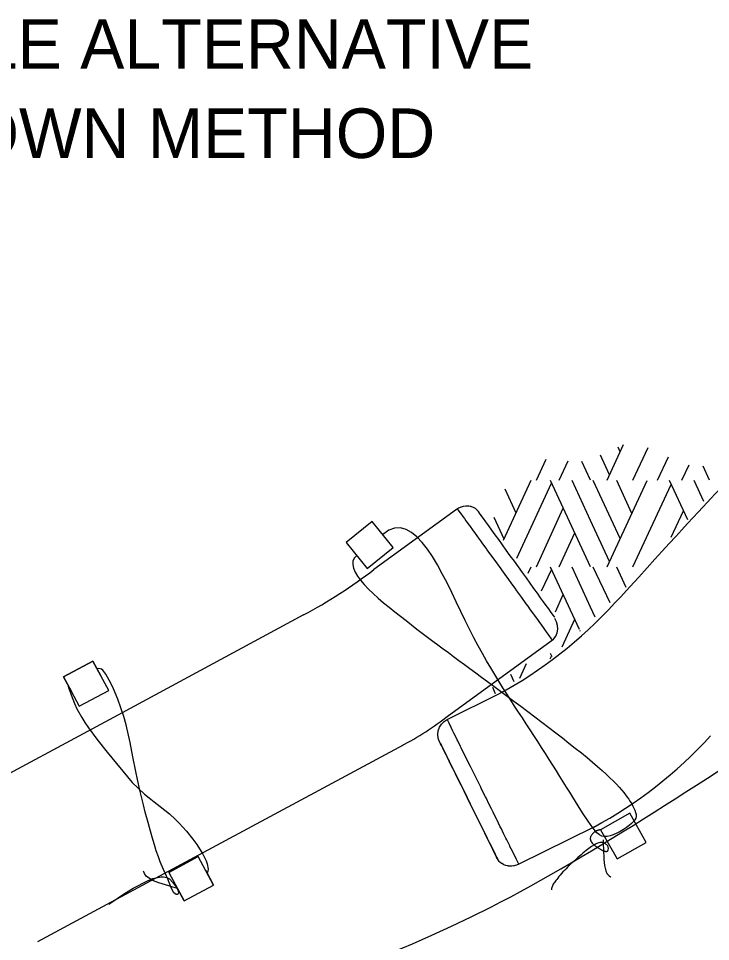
# Model space of a CAD drawing. Extents: x 99862 to 103680, y 99470 to 102076.
# Drawn here: x 100169.1 to 100392.4, y 101460 to 101757.9 of the extents above; entities that cross this region are included whole.
import ezdxf

# ---------------------------------------------------------------- set-up
doc = ezdxf.new("R2010")
doc.units = 0
for name, color, linetype in [('Level 10', 7, 'Continuous'), ('Level 11', 7, 'Continuous'), ('Level 17', 7, 'Continuous'), ('Level 20', 7, 'Continuous'), ('Level 4', 7, 'Continuous'), ('Level 6', 7, 'Continuous'), ('Level 8', 7, 'Continuous')]:
    doc.layers.add(name, color=color, linetype=linetype)

msp = doc.modelspace()

# ---------------------------------------------------------------- linework, layer by layer
at = {"layer": 'Level 10'}
msp.add_line((100327.99, 101542.55), (100327.99, 101542.55), dxfattribs=at)
at = {"layer": 'Level 11'}
for p, q in [((100359.08, 101608.87), (100364.39, 101620.37)), ((100363.32, 101618.05), (100362.61, 101619.55)), ((100367.38, 101608.87), (100372.3, 101619.43)), ((100359.85, 101610.6), (100356.9, 101616.92)), ((100375.34, 101608.87), (100378.85, 101616.43)), ((100336.24, 101608.87), (100339.34, 101615.67)), ((100343.59, 101608.87), (100346.46, 101615.17)), ((100353.71, 101608.87), (100350.94, 101614.86)), ((100383.21, 101608.87), (100385.49, 101613.83)), ((100392.13, 101608.87), (100390.02, 101613.39)), ((100325.64, 101589.47), (100334.59, 101608.87)), ((100329.92, 101583.75), (100341.08, 101607.92)), ((100353.71, 101580.93), (100340.82, 101608.79)), ((100353.71, 101595.81), (100347.74, 101608.79)), ((100363.32, 101590.1), (100354.58, 101608.79)), ((100359.08, 101580.93), (100371.97, 101608.79)), ((100367.04, 101598.15), (100362.19, 101608.79)), ((100367.38, 101580.93), (100379.75, 101607.49)), ((100385.09, 101596.03), (100379.15, 101608.79)), ((100390.32, 101602.03), (100387.19, 101608.79)), ((100329.75, 101598.23), (100326.17, 101606.02)), ((100336.24, 101580.93), (100344.89, 101599.88)), ((100379.77, 101590.48), (100383.73, 101599.01)), ((100325.85, 101589.84), (100322.63, 101596.83)), ((100359.85, 101582.66), (100353.71, 101595.81)), ((100343.59, 101580.93), (100348.61, 101591.92)), ((100333.63, 101578.85), (100334.59, 101580.93)), ((100350.14, 101560.7), (100340.82, 101580.84)), ((100353.71, 101567.86), (100347.74, 101580.84)), ((100360, 101569.24), (100354.58, 101580.84)), ((100365.21, 101574.2), (100362.19, 101580.84)), ((100337.94, 101573.17), (100341.08, 101579.98)), ((100342.36, 101566.41), (100344.89, 101571.93)), ((100355.2, 101564.68), (100353.71, 101567.86)), ((100344.56, 101555.1), (100348.61, 101563.97)), ((100350.41, 101560.12), (100350.32, 101560.32)), ((100340.72, 101551.25), (100341.08, 101552.03)), ((100341.31, 101551.84), (100340.82, 101552.9)), ((100330.89, 101544.96), (100333.05, 101549.65)), ((100329.07, 101543.82), (100328.01, 101546.12)), ((100323.09, 101539.94), (100322.14, 101542))]:
    msp.add_line(p, q, dxfattribs=at)
at = {"layer": 'Level 17'}
msp.add_open_spline([(99904.41, 101312.2), (99973.17, 101329.36), (100131.55, 101422.53), (100314.34, 101443.21), (100464.97, 101568.49), (100562.31, 101613.81)], degree=3, dxfattribs=at)
at = {"layer": 'Level 4'}
for points in [[(100198.31, 101472.01), (100203.34, 101475.46), (100206.16, 101477.21), (100210.69, 101479.56), (100212.46, 101480.25), (100213.48, 101480.55), (100215.18, 101480.82), (100215.87, 101480.82), (100216.99, 101480.6), (100217.82, 101480.17), (100218.93, 101479.03), (100220.1, 101477.44), (100220.53, 101476.68), (100220.75, 101475.67), (100220.53, 101475.23), (100220.33, 101475.11), (100219.95, 101475.12), (100219.27, 101475.7), (100218.61, 101476.88), (100218.26, 101477.65), (100217.71, 101478.97), (100217.14, 101480.37), (100216.84, 101481.08), (100215.87, 101483.23), (100214.84, 101485.69), (100214.24, 101487.3), (100213.57, 101489.26), (100213.2, 101490.39), (100212.62, 101492.29), (100212.2, 101493.68), (100211.34, 101496.72), (100210.9, 101498.33), (100210, 101501.72), (100209.41, 101504.05), (100208.27, 101508.77), (100207.49, 101512.25), (100206.96, 101514.79), (100206, 101519.62), (100205.1, 101524.18), (100203.83, 101529.87), (100203.11, 101532.56), (100201.18, 101538.22), (100199.8, 101541.51), (100198.9, 101543.4), (100197.29, 101546.27), (100196.32, 101547.51), (100195.9, 101547.86), (100195.07, 101548.1), (100194.48, 101547.99), (100194.48, 101547.99)], [(100185.18, 101542.47), (100185.17, 101542.42), (100185.36, 101541.64), (100185.54, 101541.09), (100186.05, 101539.59), (100187.17, 101536.81), (100187.97, 101535.12), (100189.57, 101532.22), (100190.56, 101530.63), (100191.7, 101528.94), (100194.41, 101525.26), (100197.68, 101521.12), (100205.83, 101511.26)], [(100205.83, 101511.26), (100209.79, 101507.49), (100211.76, 101505.86), (100212.88, 101505.02), (100214.84, 101503.59), (100217.82, 101501.16), (100219.74, 101499.39), (100220.97, 101498.15), (100223.29, 101495.6), (100225.38, 101493.03), (100226.62, 101491.33), (100228.62, 101488.12), (100229.65, 101485.96), (100230, 101484.99), (100230.31, 101483.33), (100230.25, 101482.65), (100229.99, 101482.06)], [(100357.83, 101492.74), (100357.84, 101491.21), (100357.94, 101489.84), (100358, 101486.47), (100358.19, 101484.53), (100358.65, 101482.73), (100359.02, 101481.96), (100359.7, 101481.11), (100360.13, 101480.79), (100360.27, 101480.72)], [(100220.43, 101477.04), (100218.95, 101477.46), (100217.67, 101477.92), (100214.43, 101478.88), (100212.62, 101479.58), (100211.01, 101480.51), (100210.36, 101481.08), (100209.73, 101481.96), (100209.53, 101482.46), (100209.49, 101482.7)]]:
    msp.add_lwpolyline(points, dxfattribs=at)
for points, degree in [([(100278.24, 101584.57), (100273.09, 101580.15), (100296.03, 101561.75), (100319.29, 101544.83), (100361.92, 101513.05), (100368.7, 101501.86), (100368.84, 101498.63), (100357.83, 101491.97), (100354.02, 101496.57), (100334.27, 101528.92), (100314.19, 101557.7), (100297.17, 101600.38), (100286.64, 101591.35)], 3), ([(100356.96, 101495.98), (100355.23, 101495.98), (100352.7, 101492.43), (100359.31, 101488.14), (100359.64, 101491.29), (100355.48, 101492.58), (100341.08, 101479.07), (100341.08, 101476.62)], 2)]:
    msp.add_open_spline(points, degree=degree, dxfattribs=at)
at = {"layer": 'Level 6'}
for p, q in [((100283.25, 101595.55), (100274.85, 101588.77)), ((100290.03, 101587.14), (100283.25, 101595.55)), ((100274.81, 101587.94), (100274.81, 101587.94)), ((100274.85, 101588.77), (100281.63, 101580.36)), ((100281.63, 101580.36), (100290.03, 101587.14)), ((100183.62, 101545.37), (100193.13, 101550.49)), ((100193.13, 101550.48), (100183.62, 101545.36)), ((100193.13, 101550.48), (100193.13, 101550.49)), ((100193.13, 101550.49), (100195.68, 101545.75)), ((100193.13, 101550.49), (100193.13, 101550.49)), ((100198.24, 101541), (100193.13, 101550.48)), ((100183.62, 101545.37), (100183.62, 101545.36)), ((100186.17, 101540.63), (100183.62, 101545.37)), ((100183.62, 101545.37), (100183.62, 101545.36)), ((100183.62, 101545.36), (100188.73, 101535.88)), ((100188.73, 101535.88), (100198.24, 101541)), ((100198.24, 101541), (100198.24, 101541)), ((100188.73, 101535.88), (100188.73, 101535.88)), ((100366.34, 101501.34), (100356.96, 101495.98)), ((100371.7, 101491.96), (100366.34, 101501.34)), ((100356.96, 101495.98), (100362.32, 101486.6)), ((100362.32, 101486.6), (100371.7, 101491.95)), ((100217.61, 101482.26), (100227.12, 101487.39)), ((100229.53, 101482.91), (100232.08, 101478.17)), ((100222.58, 101473.05), (100220.02, 101477.79)), ((100222.57, 101473.06), (100232.08, 101478.18))]:
    msp.add_line(p, q, dxfattribs=at)
for points in [[(100195.68, 101545.75), (100195.68, 101545.75), (100193.13, 101550.49)], [(100193.13, 101550.49), (100193.13, 101550.49), (100193.13, 101550.49)], [(100183.62, 101545.37), (100186.17, 101540.63), (100186.17, 101540.63)], [(100183.62, 101545.37), (100183.62, 101545.37), (100183.62, 101545.37)], [(100217.61, 101482.26), (100222.57, 101473.06), (100222.58, 101473.05), (100232.08, 101478.17), (100232.08, 101478.18), (100227.12, 101487.39), (100217.61, 101482.26)], [(100232.08, 101478.17), (100232.08, 101478.17), (100227.12, 101487.39), (100227.12, 101487.39)], [(100217.61, 101482.26), (100217.61, 101482.26), (100222.57, 101473.05), (100222.57, 101473.05)], [(100232.08, 101478.17), (100232.08, 101478.17), (100229.53, 101482.91)], [(100220.02, 101477.79), (100222.57, 101473.05), (100222.57, 101473.05)]]:
    msp.add_lwpolyline(points, dxfattribs=at)
at = {"layer": 'Level 8'}
for p, q in [((100307.72, 101518.92), (100308.45, 101517.44)), ((100308.45, 101517.44), (100309.25, 101515.84)), ((100309.25, 101515.84), (100310.1, 101514.11)), ((100310.1, 101514.11), (100311, 101512.29)), ((100311, 101512.29), (100311.94, 101510.4)), ((100311.94, 101510.4), (100312.9, 101508.44)), ((100312.9, 101508.44), (100313.86, 101506.51)), ((100313.86, 101506.51), (100313.89, 101506.45)), ((100313.89, 101506.45), (100314.88, 101504.45)), ((100315.87, 101502.45), (100316.84, 101500.48)), ((100316.84, 101500.48), (100317.79, 101498.56)), ((100317.79, 101498.56), (100318.7, 101496.71)), ((100318.7, 101496.71), (100320.39, 101493.3)), ((100320.39, 101493.3), (100321.15, 101491.78)), ((100321.15, 101491.78), (100321.83, 101490.4)), ((100321.83, 101490.4), (100322.96, 101488.12)), ((100322.96, 101488.12), (100323.39, 101487.24)), ((100323.39, 101487.24), (100323.66, 101486.69))]:
    msp.add_line(p, q, dxfattribs=at)
for points in [[(100342.17, 101564.64), (100342.03, 101564.82), (100341.77, 101565.19), (100341.37, 101565.74), (100340.84, 101566.47), (100340.2, 101567.36), (100339.44, 101568.42), (100338.57, 101569.62), (100337.61, 101570.95), (100336.56, 101572.41), (100335.43, 101573.96), (100334.24, 101575.61), (100333, 101577.32), (100331.73, 101579.09), (100330.43, 101580.89), (100329.12, 101582.7), (100327.82, 101584.51), (100326.53, 101586.29), (100325.28, 101588.03), (100324.07, 101589.7), (100322.92, 101591.29), (100321.84, 101592.79), (100320.84, 101594.16), (100319.94, 101595.41), (100319.14, 101596.52), (100318.45, 101597.48), (100317.88, 101598.27), (100317.52, 101598.77), (100317.23, 101599.12), (100316.8, 101599.52), (100316.71, 101599.6), (100316.59, 101599.69), (100315.98, 101600.06), (100315.9, 101600.09), (100315.3, 101600.32), (100315.16, 101600.36), (100314.86, 101600.42), (100314.44, 101600.5), (100313.74, 101600.52), (100313.68, 101600.52), (100313.52, 101600.51), (100312.75, 101600.41), (100312.59, 101600.36), (100311.99, 101600.19), (100311.83, 101600.14), (100311.47, 101599.97), (100311.11, 101599.8), (100310.42, 101599.37), (100283.8, 101580.05)], [(100310.77, 101599.59), (100310.93, 101599.35), (100311.65, 101598.37), (100311.75, 101598.23), (100312.51, 101597.18), (100313.01, 101596.47), (100313.51, 101595.79), (100314.52, 101594.39), (100314.63, 101594.23), (100315.88, 101592.5), (100316.26, 101591.97), (100317.23, 101590.64), (100318.2, 101589.29), (100318.66, 101588.65), (100320.17, 101586.56), (100320.28, 101586.42), (100321.74, 101584.39), (100322.47, 101583.38), (100323.35, 101582.16), (100324.72, 101580.25), (100324.98, 101579.9), (100326.62, 101577.64), (100326.99, 101577.11), (100328.24, 101575.39), (100329.23, 101574.01), (100329.84, 101573.18), (100331.38, 101571.03), (100332.87, 101568.98), (100333.43, 101568.19), (100334.28, 101567.03), (100335.31, 101565.59), (100335.59, 101565.21), (100336.79, 101563.54), (100336.99, 101563.27), (100337.88, 101562.04), (100338.42, 101561.29), (100338.83, 101560.73), (100339.6, 101559.65), (100339.63, 101559.61), (100340.29, 101558.7), (100340.46, 101558.46), (100340.79, 101558.01), (100341.03, 101557.67), (100341.12, 101557.55), (100341.29, 101557.32)], [(100361.54, 101569.24), (100363.4, 101571.12)], [(100261.12, 101565.37), (100201.17, 101533.07), (100151.9, 101506.53)], [(100341.81, 101557.51), (100342.5, 101558.5), (100342.96, 101559.62), (100343.15, 101560.82), (100343.07, 101562.02), (100342.73, 101563.18), (100342.14, 101564.23)], [(100307.9, 101532.92), (100341.81, 101557.51)], [(100306.43, 101531), (100307.45, 101531.65), (100324.07, 101539.88)], [(100305, 101524.43), (100304.59, 101525.56), (100304.44, 101526.76), (100304.56, 101527.96), (100304.95, 101529.11), (100305.59, 101530.14), (100306.43, 101531)], [(100330.56, 101484.92), (100330.43, 101485.18), (100329.89, 101486.27), (100329.82, 101486.42), (100329.24, 101487.59), (100328.86, 101488.36), (100328.49, 101489.12), (100327.72, 101490.66), (100327.63, 101490.84), (100326.69, 101492.75), (100326.4, 101493.34), (100325.67, 101494.82), (100324.93, 101496.3), (100324.58, 101497.02), (100323.44, 101499.33), (100323.36, 101499.48), (100322.25, 101501.73), (100321.7, 101502.84), (100321.03, 101504.19), (100319.99, 101506.29), (100319.8, 101506.68), (100318.56, 101509.19), (100318.27, 101509.77), (100317.33, 101511.68), (100316.58, 101513.2), (100316.12, 101514.12), (100314.95, 101516.49), (100313.82, 101518.76), (100313.4, 101519.63), (100312.76, 101520.92), (100311.97, 101522.51), (100311.77, 101522.93), (100310.85, 101524.77), (100310.71, 101525.07), (100310.03, 101526.43), (100309.62, 101527.26), (100309.31, 101527.88), (100308.73, 101529.07), (100308.7, 101529.12), (100308.2, 101530.13), (100308.07, 101530.39), (100307.83, 101530.89), (100307.64, 101531.27), (100307.58, 101531.4), (100307.45, 101531.65)], [(100305, 101524.43), (100305, 101524.42), (100305.1, 101524.22)], [(100354.77, 101496.89), (100330.56, 101484.92), (100329.82, 101484.61), (100329.43, 101484.5), (100329.05, 101484.4), (100328.88, 101484.37), (100328.26, 101484.3), (100328.09, 101484.28), (100327.32, 101484.31), (100327.16, 101484.32), (100327.1, 101484.34), (100326.42, 101484.47), (100326.01, 101484.62), (100325.72, 101484.73), (100325.59, 101484.79), (100325.04, 101485.12), (100324.97, 101485.16), (100324.43, 101485.62), (100324.32, 101485.73), (100324.25, 101485.82), (100323.89, 101486.29), (100323.66, 101486.69), (100323.39, 101487.24), (100322.96, 101488.12), (100322.43, 101489.17), (100321.83, 101490.4), (100321.15, 101491.78), (100320.39, 101493.3), (100319.57, 101494.95), (100318.7, 101496.71), (100317.79, 101498.56), (100316.84, 101500.48), (100315.87, 101502.45), (100314.88, 101504.45), (100313.89, 101506.45), (100312.9, 101508.44), (100311.94, 101510.4), (100311, 101512.29), (100310.1, 101514.11), (100309.25, 101515.84), (100308.45, 101517.44), (100307.72, 101518.92), (100307.07, 101520.25), (100306.49, 101521.41), (100306, 101522.4), (100305.6, 101523.2), (100305.3, 101523.81), (100305.1, 101524.22), (100305, 101524.43)], [(100305.1, 101524.22), (100305.11, 101524.21), (100305.3, 101523.81)], [(100305.3, 101523.81), (100305.31, 101523.8), (100305.6, 101523.2)], [(100175.4, 101459.95), (100225.9, 101487.16), (100293.31, 101523.47)], [(100305.6, 101523.2), (100305.62, 101523.18), (100306.02, 101522.37), (100306.49, 101521.41)], [(100306.49, 101521.41), (100306.51, 101521.38), (100307.07, 101520.25)], [(100307.07, 101520.25), (100307.09, 101520.21), (100307.6, 101519.16), (100307.72, 101518.92)], [(100314.88, 101504.45), (100315.31, 101503.57), (100315.87, 101502.45)]]:
    msp.add_lwpolyline(points, dxfattribs=at)
for centre, radius, start, end in [((100182.04, 101712.33), 166.89, 298.2841, 307.5677), ((100615.76, 101087.41), 540, 119.7533593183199, 119.75339310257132), ((100241.79, 101618.32), 108, 298.1264, 307.7418)]:
    msp.add_arc(centre, radius, start, end, dxfattribs=at)
for centre, major_axis, ratio, start_param, end_param in [((100261.2, 101677.32), (0, 153.46), 0.921041, 3.601009, 3.930938), ((100292.11, 101634.44), (0, -153.45), 0.921099, 0.459273, 0.789201)]:
    msp.add_ellipse(centre, major_axis=major_axis, ratio=ratio, start_param=start_param, end_param=end_param, dxfattribs=at)
msp.add_open_spline([(100363.4, 101571.12), (100396.34, 101607.65), (100404.92, 101615.31), (100421.09, 101629.4), (100504.17, 101671.31), (100537.69, 101688.23)], degree=3, dxfattribs=at)

# ---------------------------------------------------------------- texts
at = {"layer": 'Level 20'}
for s, p in [('ALLOWABLE ALTERNATIVE ', (100053.45, 101741.68)), ('TIE-DOWN METHOD', (100096.77, 101712.88))]:
    msp.add_text(s, height=16, dxfattribs=at).set_placement(p)

doc.saveas('drawing.dxf')
